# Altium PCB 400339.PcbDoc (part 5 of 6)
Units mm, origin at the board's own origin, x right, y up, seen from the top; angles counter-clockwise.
Board outline 146 x 63.5 mm, 4 copper layers (Top Layer, Mid-Layer 1, Mid-Layer 2, Bottom Layer), stack 1.505 mm thick; 400 components, 261 nets, 1523 pads, 1938 vias.
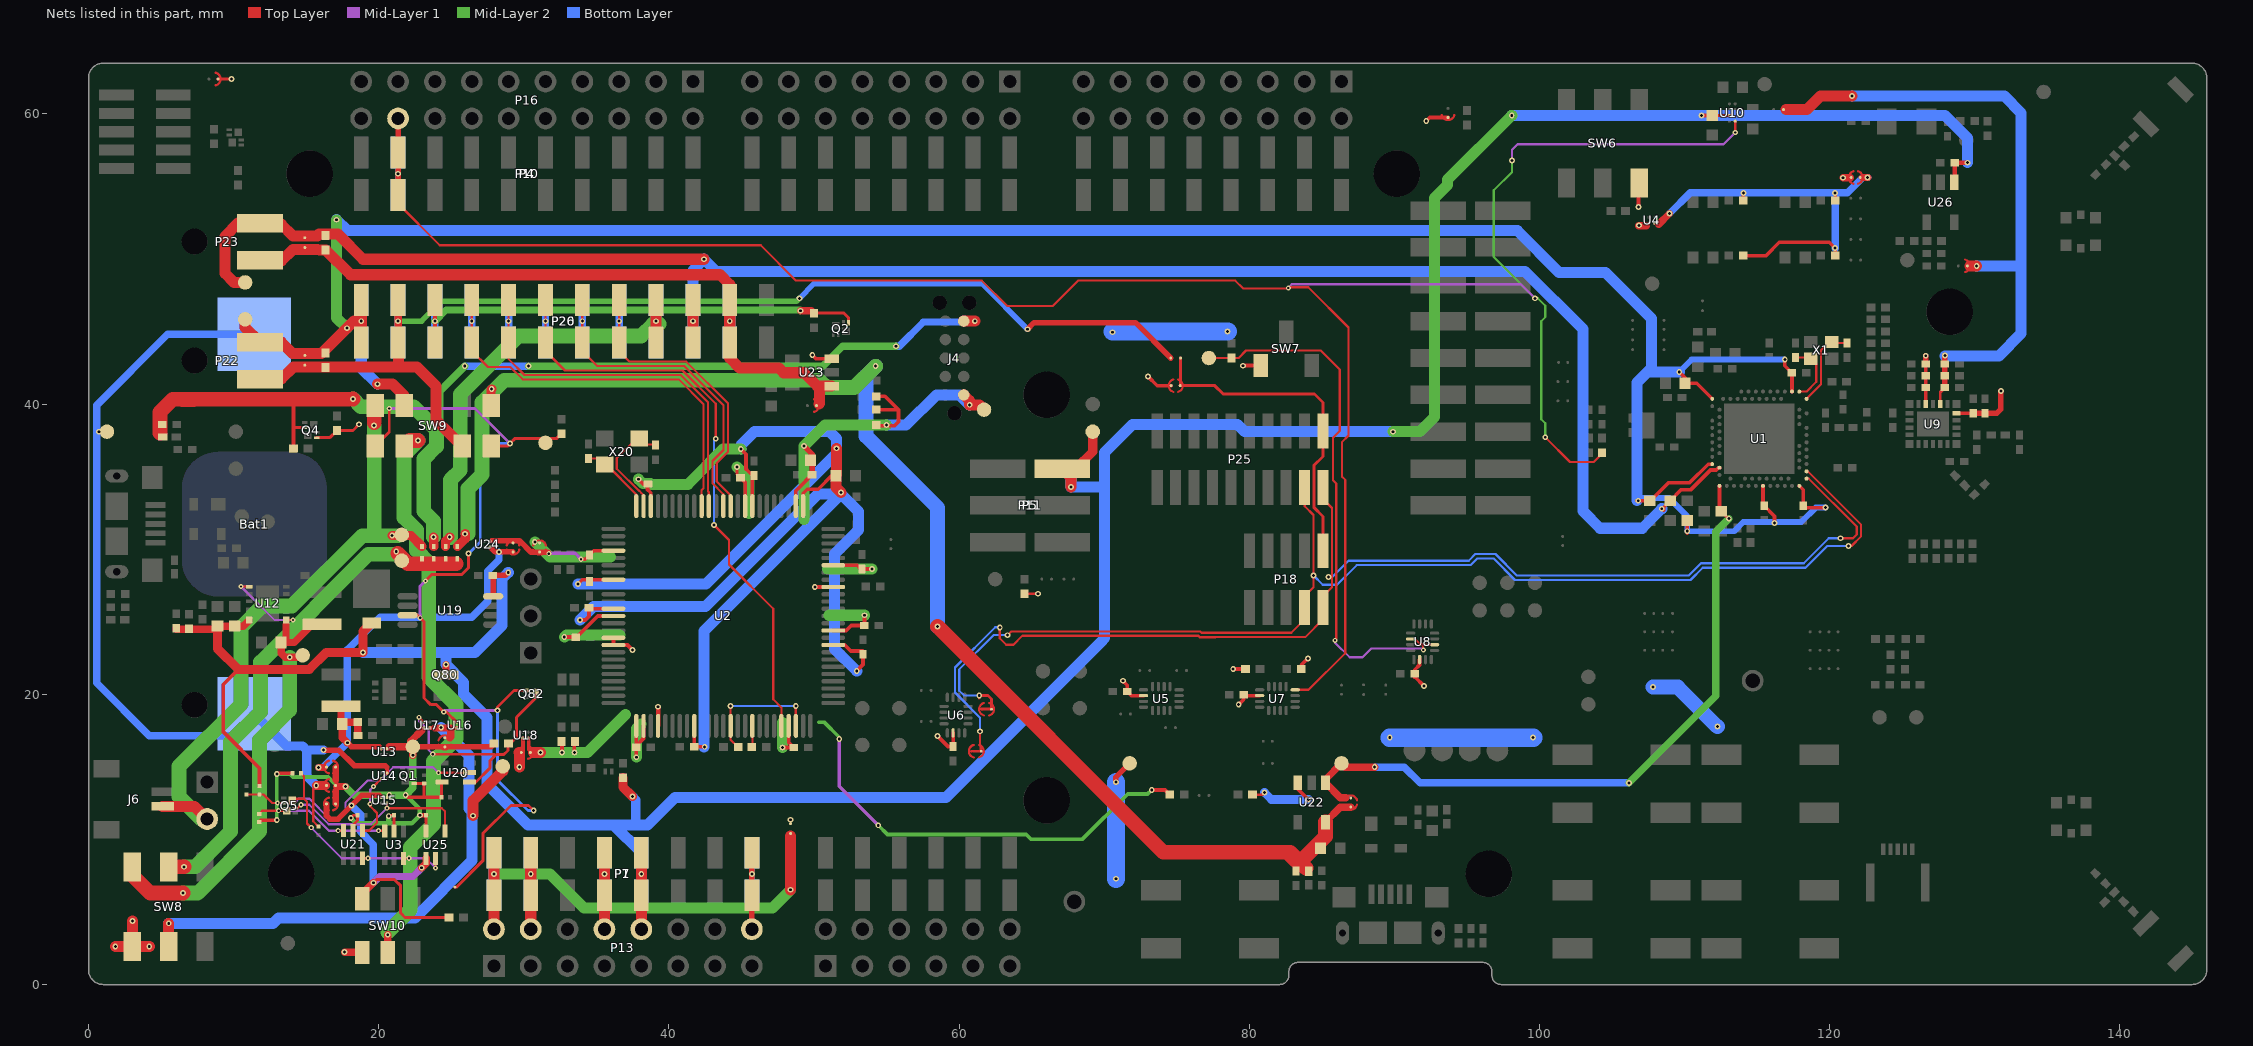
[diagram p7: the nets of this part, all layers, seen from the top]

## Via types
v1: diameter 0.4, hole 0.2, Top Layer to Bottom Layer, tented both sides, 1691 vias
v2: diameter 0.35, hole 0.15, Top Layer to Mid-Layer 1, tented both sides, 184 vias
v3: diameter 0.61, hole 0.305, Top Layer to Bottom Layer, 24 vias
v4: diameter 0.61, hole 0.305, Top Layer to Bottom Layer, tented both sides, 16 vias
v5: diameter 0.5, hole 0.3, Top Layer to Bottom Layer, tented both sides, 12 vias
v6: diameter 0.35, hole 0.15, Top Layer to Mid-Layer 1, tented top, 8 vias
v7: diameter 0.4, hole 0.2, Top Layer to Mid-Layer 1, tented top, 2 vias
v8: diameter 0.35, hole 0.15, Top Layer to Bottom Layer, tented top, 1 vias

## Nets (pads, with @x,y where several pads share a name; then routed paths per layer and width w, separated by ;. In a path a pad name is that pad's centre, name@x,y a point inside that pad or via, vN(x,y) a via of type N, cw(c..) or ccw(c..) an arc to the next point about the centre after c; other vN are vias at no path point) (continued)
SDA: P4.9 P10.9 P16.18 R1.1 U7.8 U10.D2 | length 167.8
  Top Layer w0.152: P4.9@21.336,54.415 21.336,53.823 24.206,50.952 46.329,50.952 48.767,48.514 61.568,48.514 63.321,46.761 66.452,46.761 68.205,48.514 79.037,48.514 79.579,47.972 82.649,47.972 v2(82.693,48.016) 82.736,48.059 84.071,48.059 86.843,45.288 86.843,37.838 86.385,37.38 86.385,35.009 86.614,34.78 86.614,22.835 84.089,20.31 U7.8@83.165,20.31 ; v1(100.406,37.719) 102.108,36.017 103.751,36.017 104.318,36.584 R1.1@104.318,36.66 ; v2(113.497,58.725) U10.D2@113.497,59.5
  Top Layer w0.381: P4.9@21.336,54.415 v1(21.336,55.88) P4.9@21.336,57.345 P16.18@21.336,59.69
  Mid-Layer 1 w0.152: v2(82.693,48.016) 82.937,48.26 98.73,48.26 v1(99.695,47.295) ; v1(98.12,56.792) 98.12,57.545 98.487,57.912 112.684,57.912 v2(113.497,58.725)
  Mid-Layer 2 w0.152: v1(98.12,56.792) 98.12,56.007 96.85,54.737 96.85,50.14 v1(99.695,47.295) 99.892,47.295 100.404,46.783 100.404,45.997 100.127,45.72 100.127,38.964 100.406,38.684 v1(100.406,37.719)
  Bottom Layer w0.381: P10.9@21.336,54.415 v1(21.336,55.88) P10.9@21.336,57.345
SH_GND_DETECT: P20.8 P26.8 U2.62 | length 23.2
  Top Layer w0.152: P20.8@36.576,47.185 P20.8@36.576,44.255 36.576,43.637 37.282,42.931 41.193,42.931 44.069,40.056 44.069,36.711 43.307,35.949 43.307,34.671 44.254,33.724 U2.62@44.254,32.975
  Bottom Layer w0.508: P26.8@36.576,44.255 v1(36.576,45.72) P26.8@36.576,47.185
SH_RESET: P20.7 P26.7 U2.63 | length 25.3
  Top Layer w0.152: P20.7@34.036,47.185 P20.7@34.036,44.255 34.036,43.663 35.072,42.627 41.067,42.627 43.764,39.93 43.764,36.837 43.002,36.075 43.002,34.545 43.754,33.793 U2.63@43.754,32.975
  Bottom Layer w0.508: P26.7@34.036,44.255 v1(34.036,45.72) P26.7@34.036,47.185
SH_SWDCLK: P20.5 P26.5 U2.65 | length 29.2
  Top Layer w0.152: P20.5@28.956,47.185 28.956,43.104 30.048,42.012 40.814,42.012 42.697,40.128 42.697,33.987 42.754,33.931 U2.65@42.754,32.975
  Bottom Layer w0.508: P26.5@28.956,44.255 v1(28.956,45.72) P26.5@28.956,47.185
SH_SWDIO: P20.4 P26.4 U2.66 | length 30.9
  Top Layer w0.152: P20.4@26.416,44.255 26.416,43.67 27.53,42.556 29.072,42.556 29.921,41.707 40.688,41.707 42.393,40.002 42.393,34.2 42.254,34.061 U2.66@42.254,32.975 ; P20.4@26.416,44.348 P20.4@26.416,47.185
  Bottom Layer w0.508: P26.4@26.416,44.255 v1(26.416,45.72) P26.4@26.416,47.185
SH_SWO: P20.6 P26.6 U2.21 | length 43.9
  Top Layer w0.152: P20.6@31.496,47.185 v1(31.496,45.72) P20.6@31.496,44.255 31.496,43.663 32.837,42.322 40.941,42.322 43.231,40.032 v1(43.231,37.617) ; v1(43.104,31.674) 44.145,30.632 44.145,28.955 47.193,25.907 47.193,19.66 47.754,19.099 U2.21@47.754,17.825
  Bottom Layer w0.152: v1(43.104,31.674) 43.104,37.49 v1(43.231,37.617)
  Bottom Layer w0.508: P26.6@31.496,44.255 v1(31.496,45.72) P26.6@31.496,47.185
SH_VTG: P20.3 P26.3 Q2.4 R22.1 | length 38.2
  Top Layer w0.152: P20.3@23.876,44.255 P20.3@23.876,47.185
  Top Layer w0.203: R22.1@49.996,46.271 52.072,46.271 52.387,45.955 Q2.4@52.387,45.62
  Top Layer w0.254: P20.3@23.876,44.255 v1(23.876,45.72) P20.3@23.876,47.185
  Top Layer w0.508: v1(49.073,46.436) 49.83,46.436 R22.1@49.996,46.271
  Mid-Layer 2 w0.508: v1(23.876,45.72) 24.643,46.487 49.068,46.487 49.073,46.482 v1(49.073,46.436)
  Bottom Layer w0.508: P26.3@23.876,44.255 v1(23.876,45.72) P26.3@23.876,47.185
SWDCLK: P18.4 P25.4 SB55.1 U1.AA24 | length 86.2
  Top Layer w0.152: v1@61.374,19.736 61.392,19.754 v1(61.392,19.914) ; v1(63.349,24.078) 63.607,24.335 76.624,24.335 76.71,24.249 82.897,24.249 83.82,25.171 P18.4@83.82,25.99 83.82,26.773 84.429,27.381 v1(84.429,28.194) 84.429,32.36 83.82,32.968 P25.4@83.82,34.245 ; U1.AA24@118.414,35.367 118.496,35.367 122.174,31.689 122.174,30.886 121.514,30.226
  Top Layer w0.203: v1(61.392,19.914) 62.001,19.914 62.238,19.677 62.238,19.327 SB55.1@62.238,18.974
  Bottom Layer w0.152: v1(61.392,19.914) 60.35,19.914 60.02,20.244 60.02,21.718 62.385,24.083 63.344,24.083 v1(63.349,24.078) ; v1(84.429,28.194) 85.064,27.559 86.056,27.559 87.402,28.905 95.25,28.905 95.707,29.362 96.844,29.362 98.322,27.884 110.415,27.884 111.258,28.728 118.338,28.728 119.837,30.226 v1(121.31,30.226)
SWDIO: P18.2 P25.2 SB54.1 U1.AC24 | length 88.3
  Top Layer w0.152: v1(61.443,17.45) 61.443,16.505 61.493,16.454 61.493,16.111 SB54.1@61.526,16.078 ; v1(62.81,24.616) 62.81,23.862 63.254,23.419 63.754,23.419 64.366,24.03 76.498,24.03 76.589,23.939 77.682,23.939 77.687,23.944 83.863,23.944 85.09,25.171 P18.2@85.09,25.99 85.09,26.773 85.699,27.381 85.699,32.843 85.09,33.452 P25.2@85.09,34.245 ; U1.AC24@118.414,34.867 118.565,34.867 121.869,31.563 121.869,31.012 121.616,30.759 v1(120.752,30.759)
  Bottom Layer w0.152: v1(61.443,17.45) 61.443,18.394 59.715,20.121 59.715,21.845 62.487,24.616 v1(62.81,24.616) ; 85.725,28.092 86.843,29.21 95.124,29.21 95.581,29.667 96.967,29.667 98.448,28.187 110.29,28.187 111.133,29.03 118.213,29.03 119.942,30.759 v1(120.752,30.759)
  other v1: 85.471,28.092
TCKOUT: R28.1 U2.14 U2.23 | length 8.9
  Top Layer w0.152: v1(44.254,19.197) 44.254,16.876 R28.1@44.772,16.358 ; v1(48.75,19.197) 48.75,17.837 48.758,17.829 U2.23@48.754,17.825
  Bottom Layer w0.152: v1(44.254,19.197) v1(48.75,19.197)
TMSOUT: R29.1 U2.17 | length 1.4
  Top Layer w0.152: R29.1@45.754,16.385 U2.17@45.754,17.825
TRACE_SW: R4.1 TP23.1 U8.2 U8.10 | length 37.8
  Top Layer w0.152: TP23.1@77.216,43.18 79.273,43.18 79.785,43.691 84.934,43.691 86.233,42.393 86.233,38.151 85.776,37.694 85.776,34.756 86.004,34.528 86.004,23.825 v2(85.903,23.724) ; U8.10@91.123,23.822 91.418,23.822 91.818,23.422 91.973,23.422 ; v2@91.973,23.114 91.973,23.422 ; U8.2@92.773,23.422 91.973,23.422
  Mid-Layer 1 w0.152: v2(85.903,23.724) 85.903,23.579 86.926,22.555 87.808,22.555 88.417,23.165 91.923,23.165 v2@91.999,23.089
  other v2: 91.999,23.063
V5V: C81.2 C82.2 C83.2 C85.2 C95.2 C97.2 D84.1 P1.5 P5.2 P7.5 P11.2 P13.10 Q80.2 R80.2 R83.1 R93.1 TP36.1 U10.C1 U12.10 U19.8 U26.1 | length 227.8
  Top Layer w0.203: C95.2@111.922,59.896 111.927,59.9 U10.C1@113.097,59.9
  Top Layer w0.254: 10.312,21.717 9.296,20.701 9.296,17.399 11.786,14.91 11.786,13.674 R83.1@11.782,13.671
  Top Layer w0.305: v1(111.17,59.896) C95.2@111.922,59.896 ; U26.1@128.598,55.292 128.631,55.325 C97.2@128.631,56.635 129.501,56.635 v1(129.508,56.642)
  Top Layer w0.381: C85.2@27.856,28.194 28.727,28.194 v1(28.931,28.397) ; U19.8@27.893,26.756 C85.2@27.893,28.157
  Top Layer w0.508: C81.2@6.045,24.544 6.045,24.473 C83.2@8.663,24.473 ; C83.2@8.89,24.7 C82.2@10.084,24.7 10.66,24.7 U12.10@11.04,25.079 ; Q80.2@24.639,21.336 v1(24.639,22.046)
  Top Layer w0.635: C83.2@8.89,24.7 8.89,23.139 10.312,21.717 15.215,21.717 16.383,22.885 v1(18.923,22.885) 18.923,24.334 D84.1@19.507,24.918 ; R93.1@36.83,14.257 36.83,13.614 v1(37.49,12.954) ; P5.2@67.119,35.56 68.047,35.56 69.215,36.728 TP36.1@69.215,38.1
  Top Layer w0.762: P13.10@38.1,3.81 P1.5@38.1,6.155 v1(38.1,7.62) P1.5@38.1,9.085 ; P5.2@67.119,35.56 67.722,34.957 v1(67.722,34.296)
  Mid-Layer 2 w0.762: v1(89.916,38.1) 91.767,38.1 92.773,39.106 92.773,54.206 93.675,55.108 93.675,55.474 v1(98.095,59.893)
  Bottom Layer w0.508: 21.857,22.948 21.92,22.885 ; 24.639,22.81 24.714,22.885
  Bottom Layer w0.635: v1(37.49,12.954) 37.719,12.725 37.719,10.998
  Bottom Layer w0.762: v1(18.923,22.885) 21.92,22.885 24.714,22.885 26.645,22.885 28.499,24.74 28.499,27.965 v1(28.931,28.397) ; 24.639,22.81 v1(24.639,22.046) 25.857,20.828 25.857,20.015 27.47,18.402 27.47,13.83 30.302,10.998 36.187,10.998 ; P7.5@38.1,6.155 v1(38.1,7.62) P7.5@38.1,9.085 36.187,10.998 ; P11.2@67.722,35.56 v1(67.722,34.296) 70.028,34.296 ; v1(89.916,38.1) 79.68,38.1 79.179,38.6 71.951,38.6 70.028,36.678 70.028,34.296 ; v1(98.095,59.893) 127.967,59.893 129.508,58.352 v1(129.508,56.642) ; 36.187,10.998 37.719,10.998 38.532,10.998 40.437,12.903 59.097,12.903 69.901,23.707 69.901,23.741 70.028,23.868 70.028,34.296
VBAT: Bat1.1 R18.1 SB35.2 TP26.1 U14.A1 | length 62.5
  Top Layer w0.152: v1(15.697,13.716) 15.482,13.501 15.482,11.244 R18.1@15.85,10.877
  Top Layer w0.254: U14.A1@20.571,14.576 20.571,14.959
  Top Layer w0.381: v1(16.205,16.154) 17.245,16.154 18.314,15.085 20.445,15.085 20.571,14.959
  Top Layer w0.61: v1(15.697,13.716) 16.226,13.716 SB35.2@16.332,13.716
  Bottom Layer w0.508: Bat1.1@11.43,18.654 9.921,17.145 4.191,17.145 0.559,20.777 0.559,39.929 5.446,44.816 Bat1.1@11.43,44.816
  Bottom Layer w0.635: Bat1.1@11.43,18.654 13.65,16.434 14.757,16.434 15.037,16.154 ; v1(15.697,13.716) 15.037,14.376 15.037,16.154 ; v1(16.205,16.154) 15.037,16.154
  other v1: 0.711,38.1
VBAT_EN: U14.B2 U21.4 | length 4.8
  Top Layer w0.152: U21.4@18.887,10.602 19.33,10.602 19.882,11.154 19.882,11.817 19.412,12.287 v6(19.412,12.443) v6@19.412,12.531 ; v6(19.645,13.65) U14.B2@20.171,14.176
  Mid-Layer 1 w0.152: v6(19.412,12.443) 19.412,13.418 v6(19.645,13.65)
VBOOST_SRC: C80.2 L80.2 SW8.6 TP28.1 U12.1 U12.6 | length 37.2
  Top Layer w0.152: v2(10.516,27.432) 11.056,27.432 U12.6@11.074,27.414 ; U12.1@13.614,25.114 v2(14.09,25.114)
  Top Layer w0.508: 13.614,24.816 13.614,23.871 C80.2@13.315,23.571 ; TP28.1@14.757,22.682 14.63,22.555 v1(13.868,22.555) 13.538,22.555 13.273,22.82 C80.2@13.273,23.571 C80.2@13.315,23.571 ; L80.2@16.104,24.833 15.435,24.833 14.173,23.571 C80.2@13.315,23.571
  Top Layer w1.016: SW8.6@3.028,8.109 3.028,7.529 4.258,6.299 v1(6.518,6.299)
  Mid-Layer 1 w0.152: v2(10.516,27.432) 12.834,25.114 v2(14.09,25.114)
  Mid-Layer 2 w1.016: v1(6.518,6.299) 7.518,6.299 11.786,10.566 11.786,16.84 13.868,18.923 v1(13.868,22.555)
VBOOST_SRC': D80.1 D81.1 D82.1 D83.1 SW8.5 TP32.1 | length 34.7
  Top Layer w1.016: SW8.5@5.528,8.109 v1(6.576,8.109) ; v1@21.311,29.718 22.022,29.007 25.349,29.007
  Mid-Layer 2 w1.016: v1(6.576,8.109) 7.347,8.109 9.779,10.541 9.779,16.713 11.862,18.796 11.862,22.225 19.291,29.654 21.336,29.654
  other v1: 21.209,29.845
VBUS: C69.2 D80.2 FB61.2 J4.5 Q4.2 R40.1 | length 77.7
  Top Layer w0.203: 14.13,38.384 14.144,38.397 Q4.2@14.909,38.397
  Top Layer w0.254: 13.452,40.367 14.13,40.367 14.13,40.329 14.13,38.384 R40.1@14.13,36.932
  Top Layer w0.635: v1(23.774,30.836) 23.8,30.81 D80.2@23.8,30.186
  Top Layer w0.762: J4.5@60.325,45.72 v1(61.087,45.72)
  Top Layer w1.016: 4.923,38.011 4.923,39.441 5.811,40.329 6.444,40.329 6.452,40.322 7.251,40.322 7.259,40.329 13.414,40.329 ; 13.452,40.329 14.13,40.329 18.206,40.329 v1(18.237,40.361)
  Mid-Layer 2 w0.508: 23.978,38.252 24.206,38.481 24.206,40.894 v1(25.933,42.621) ; v1(30.328,42.621) 50.597,42.621 51.968,43.993 v1(55.651,43.993)
  Mid-Layer 2 w1.016: v1(18.237,40.361) 18.771,39.827 22.403,39.827 23.978,38.252 23.978,37.084 23.114,36.22 23.114,32.614 23.774,31.953 v1(23.774,30.836)
  Bottom Layer w0.508: v1(25.933,42.621) v1(30.328,42.621) ; v1(55.651,43.993) 55.88,43.993 57.545,45.658 61.025,45.658 v1(61.087,45.72)
VBUS_NRF: C21.1 SB80.1 TP38.1 U1.AD2 U22.1 | length 47.6
  Top Layer w0.25: U1.AD2@112.414,34.367 112.414,32.742 C21.1@112.539,32.617 v1@113.053,32.103
  Top Layer w0.508: 86.656,12.878 86.272,12.878 U22.1@85.253,13.898 85.253,14.133 TP38.1@86.36,15.24 86.614,14.986 v1(88.646,14.986)
  Mid-Layer 2 w0.508: v1(106.172,13.894) 112.166,19.888 112.166,31.217 v1(113.055,32.106)
  Bottom Layer w0.508: v1(88.646,14.986) 90.678,14.986 91.77,13.894 v1(106.172,13.894)
VBUS_NRF': C68.2 C91.2 D81.2 FB60.2 SB80.2 SW9.8 U22.5 | length 100
  Top Layer w0.508: U22.5@85.253,11.198 86.272,12.217 SB80.2@86.995,12.217
  Top Layer w0.635: D81.2@25.425,30.186 25.959,30.719 v1(25.959,31.064) ; SW9.8@27.749,39.906 27.749,41.008 v1(27.788,41.046)
  Top Layer w1.016: v1(58.522,24.673) 74.076,9.119 82.634,9.119 ; 83.497,8.44 85.253,10.196 U22.5@85.253,11.198 ; 83.666,8.271 83.315,8.621 83.223,8.529 82.634,9.119 ; FB60.2@83.91,8.026 82.818,9.119 82.634,9.119
  Mid-Layer 2 w1.016: 26.162,31.064 26.162,34.188 27.127,35.154 27.127,40.132 28.651,41.656 50.368,41.656 50.876,41.148 52.781,41.148 v1(54.254,42.621)
  Bottom Layer w1.016: v1(54.254,42.621) 53.594,41.961 53.594,37.795 58.522,32.868 v1(58.522,24.673)
VCC2: C56.2 C57.2 C58.2 SB27.1 SB28.1 U9.14 | length 45.2
  Top Layer w0.203: U9.14@127.628,40.005 127.628,40.828 C56.2@127.948,41.148
  Top Layer w0.381: C56.2@127.948,41.148 C57.2@127.948,41.961 C58.2@127.948,42.774 v1(127.948,43.358)
  Top Layer w0.762: 116.986,60.302 118.449,60.302 119.386,61.239 v1(121.549,61.239) ; 129.671,49.53 v1(130.138,49.53)
  Bottom Layer w0.762: v1(121.549,61.239) 132.045,61.239 133.206,60.078 133.206,44.854 131.684,43.332 v1@127.948,43.332 ; v1(130.138,49.53) 133.182,49.53
VCORE: C24.2 C26.2 C32.1 C33.2 C35.2 C39.2 C40.2 U2.9 U2.34 U2.52 U2.59 U2.73 U2.83 U2.87 | length 120.1
  Top Layer w0.254: v1(33.747,27.598) 34.038,27.889 U2.83@36.168,27.889 ; v1(33.874,25.121) 34.232,25.121 34.501,25.389 C24.2@34.501,25.959 ; C24.2@34.67,25.9 U2.87@36.179,25.9 ; v1(37.897,34.823) 38.227,34.493 C32.1@38.531,34.493 ; C32.1@38.555,34.493 C32.1@38.531,34.493 ; U2.73@38.754,32.975 38.754,33.89 38.531,34.113 C32.1@38.531,34.493 ; C33.2@41.75,16.383 v1(42.469,16.383) ; C33.2@41.754,16.4 U2.9@41.754,17.825 ; v1(44.958,36.906) 45.314,36.551 45.314,35.525 45.466,35.373 C35.2@45.808,35.031 ; U2.59@45.754,32.975 45.754,34.977 C35.2@45.808,35.031 ; C35.2@45.862,35.085 C35.2@45.808,35.031 ; U2.52@49.254,32.975 49.254,33.861 49.531,34.138 50.292,34.138 51.232,35.077 C39.2@51.522,35.077 ; U2.34@51.329,23.4 52.13,23.4 52.543,22.987 C40.2@53.338,22.987 ; v1(52.949,21.615) 53.381,22.047 C40.2@53.381,22.766 ; C40.2@53.363,22.827 C40.2@53.363,22.987
  Top Layer w0.762: v1(51.562,36.957) 51.562,35.117 C39.2@51.522,35.077 51.522,34.254 v1(51.867,33.909)
  Mid-Layer 2 w0.762: v1(37.897,34.823) 38.202,34.519 38.718,34.519 38.769,34.468 41.3,34.468 43.739,36.906 v1(44.958,36.906)
  Bottom Layer w0.762: v1(33.747,27.598) 42.558,27.598 51.562,36.601 v1(51.562,36.957) 51.562,37.643 51.079,38.125 45.898,38.125 44.958,37.186 v1(44.958,36.906) ; v1(33.874,25.121) 34.813,26.06 42.535,26.06 50.292,33.817 v1@51.867,33.817 ; v1@42.416,16.383 42.408,16.391 42.408,24.359 v1@51.867,33.817 ; v1(52.949,21.615) 51.425,23.139 51.425,29.671 53.076,31.322 53.076,32.608 v1@51.867,33.817
VDBG: P18.1 P25.1 SB59.1 SB60.1 | length 23
  Top Layer w0.203: SB60.1@75.268,43.18 75.268,41.607 75.268,41.3 SB59.1@75.242,41.275 75.417,41.275 77.622,41.275 78.207,40.691 84.506,40.691 85.09,40.107 P25.1@85.09,38.145 85.09,36.398 84.455,35.763 84.455,32.893 85.09,32.258 P18.1@85.09,29.89
VDD: C23.2 C42.2 C45.2 C48.2 C50.2 C53.2 C54.2 C70.2 C71.2 Q4.4 R41.1 R52.1 R53.1 R54.2 R68.2 SB9.1 SB31.1 SB37.2 SB38.2 SB47.1 SB59.2 SW6.6 SW7.3 SW8.3 SW10.6 TP37.1 U4.A2 U5.14 U6.14 U7.14 U8.14 U9.11 U9.16 U18.A2 U22.3 U23.3 | length 77.1
  Top Layer w0.2: SB47.1@8.923,62.408 v1(9.855,62.408) ; R41.1@17.12,38.184 18.22,38.184 v1(18.644,38.608) ; R68.2@64.516,26.932 v1(65.448,26.932) ; R54.2@80.231,13.081 80.899,13.081 v1(81.051,13.233)
  Top Layer w0.203: Q4.4@15.724,37.687 16.623,37.687 R41.1@17.12,38.184
  Top Layer w0.254: 29.941,15.992 U18.A2@29.941,16.95 ; v1(49.886,43.383) 50.129,43.139 U23.3@51.21,43.139 ; v1(58.522,17.12) 59.241,16.4 C45.2@59.588,16.4 59.592,16.404 U6.14@59.592,17.342 ; v1(71.306,20.938) 71.306,20.922 71.595,20.633 C42.2@71.595,20.193 71.88,19.907 U5.14@72.707,19.907 ; v1(73.025,41.91) 73.66,41.275 74.443,41.275 SB59.2@74.618,41.275 ; v1@78.892,21.717 78.918,21.742 R53.1@79.739,21.742 ; v1(79.273,19.304) 79.621,19.652 C48.2@79.621,19.964 79.675,19.91 U7.14@80.715,19.91 ; v1(79.578,42.647) 79.597,42.665 SW7.3@80.8,42.665 ; U22.3@83.353,13.898 83.353,13.472 v1(84.074,12.751) ; R52.1@83.583,21.742 83.583,22.014 v1(84.049,22.479) v1@84.074,22.504 ; C50.2@91.389,21.192 91.508,21.311 C50.2@91.407,21.412 ; U8.14@91.748,22.397 91.737,22.386 91.737,22.021 91.407,21.69 C50.2@91.407,21.412 ; v1(92.05,20.574) 91.411,21.213 91.407,21.217 C50.2@91.407,21.412 ; v1(92.202,59.512) 92.448,59.759 SB31.1@93.701,59.759 ; v1(106.832,53.594) 106.832,54.948 SW6.6@106.869,54.984 ; 107.292,52.225 U4.A2@107.537,52.47 ; U9.16@126.628,40.005 C23.2@126.628,42.774 ; U9.11@128.753,39.38 129.894,39.38 C70.2@129.896,39.378
  Top Layer w0.381: v1(70.815,13.945) 70.815,14.3 TP37.1@71.755,15.24 ; C23.2@126.628,42.774 v1(126.628,43.335) ; C70.2@129.896,39.378 C71.2@130.708,39.378 131.537,39.378 131.81,39.651 v1(131.81,40.897)
  Top Layer w0.508: v1(17.653,2.235) 17.674,2.214 SW10.6@18.875,2.214 ; v1@106.858,52.299 107.366,52.299 ; v1(120.929,55.608) SB9.1@121.433,55.608
  Top Layer w0.762: v1(1.848,2.628) v1(4.185,2.628) ; SW8.3@3.027,2.559 v1(3.027,4.369) ; 29.679,15.992 29.693,15.979 v1(29.693,14.986)
  Bottom Layer w0.61: v1(81.051,13.233) 81.534,12.751 v1(84.074,12.751)
  Bottom Layer w1.016: v1(107.823,20.498) 109.55,20.498 v1(112.268,17.78)
  Bottom Layer w1.27: v1@70.587,45.009 v1(78.511,45.009) ; v1(70.815,7.29) v1(70.815,13.945) ; v1(89.687,17.018) v1(99.568,17.018)
  other v1: 48.387,11.354 78.892,21.742 70.587,44.958 106.858,52.324
VDD_HV: C19.1 P20.10 P23.1 P26.10 R91.2 SB41.1 TP25.1 U1.Y2 | length 134.4
  Top Layer w0.25: v1@108.562,32.708 108.562,32.891 C19.1@109.014,33.342 109.783,34.112 110.447,34.112 111.793,35.458 111.989,35.458 112.179,35.459 112.337,35.617 U1.Y2@112.414,35.617
  Top Layer w0.762: TP25.1@10.795,48.387 10.033,48.387 9.398,49.022 9.398,51.562 10.306,52.47 P23.1@11.811,52.47 ; P23.1@11.811,52.4 13.284,52.4 14.089,51.595 15.781,51.595 15.9,51.714 17.196,51.714 18.923,49.987 v1(42.418,49.987) ; P20.10@41.656,44.255 v1(41.656,45.72) P20.10@41.656,47.185
  Bottom Layer w0.762: P26.10@41.656,44.255 v1(41.656,45.72) P26.10@41.656,47.185 41.656,49.225 v1(42.418,49.987) 43.256,49.149 99.023,49.149 102.997,45.175 102.997,32.639 104.188,31.448 107.089,31.448 v1(108.433,32.791)
VDD_HV': P20.11 P23.2 P26.11 R91.1 SB41.2 SB81.1 U23.1 | length 50.7
  Top Layer w0.762: P23.2@11.811,49.86 13.284,49.86 14.089,50.665 15.781,50.665 ; 15.91,50.613 16.349,50.613 18.042,48.92 43.51,48.92 44.196,48.235 P20.11@44.196,47.185 v1(44.196,45.72) P20.11@44.196,44.255 44.196,43.18 44.882,42.494 47.585,42.494 47.915,42.164 49.301,42.164 50.226,41.239 ; 50.333,40.016 50.368,40.051 50.368,41.097 50.226,41.239 ; U23.1@51.21,41.239 50.226,41.239
  Bottom Layer w0.762: P26.11@44.196,44.255 v1(44.196,45.72) P26.11@44.196,47.185
VDD_NRF: C6.1 C7.1 C8.1 C12.1 C14.1 L4.1 P20.1 P22.1 P26.1 R90.2 SB40.1 SW9.6 TP24.1 U1.A22 U1.AD14 U1.AD23 U1.B1 U1.W1 | length 179.9
  Top Layer w0.25: v1@106.714,33.342 v1(106.815,33.342) C6.1@107.613,33.342 107.664,33.342 108.916,34.595 110.371,34.595 111.641,35.865 U1.W1@111.914,35.865 ; v1(109.639,42.217) 110.039,41.817 C14.1@110.039,41.444 110.837,41.444 U1.B1@111.914,40.367 ; v1@110.189,31.117 L4.1@110.189,31.992 ; C7.1@115.414,32.992 U1.AD14@115.414,34.367 ; C7.1@115.49,32.992 116.205,32.277 116.205,32.004 ; v1(116.915,43.067) 116.915,42.641 C12.1@117.389,42.167 117.414,42.142 U1.A22@117.414,40.867 ; U1.AD23@117.914,34.367 118.189,34.092 C8.1@118.189,32.992 118.313,32.868 v1(119.71,32.868)
  Top Layer w0.762: TP24.1@10.795,45.847 10.795,45.286 P22.1@11.811,44.27 13.284,44.27 14.064,43.49 16.058,43.49 v1(17.805,45.237) 18.288,45.72 v1(18.796,45.72) ; P20.1@18.796,44.255 v1(18.796,45.72) ; P20.1@18.796,47.185 v1(18.796,45.72) ; v1(19.914,41.377) 20.955,41.377 21.749,40.583 SW9.6@21.749,39.906
  Mid-Layer 2 w0.762: v1@17.094,52.685 17.094,45.949 v1(17.805,45.237)
  Bottom Layer w0.4: v1@106.714,33.342 106.731,33.36 106.894,33.522 108.946,33.522 110.189,32.28 v1@110.189,31.318 ; v1(109.639,42.217) 110.489,43.067 v1@116.839,43.067 ; v1(110.189,31.244) 113.427,31.244 114.054,31.871 118.054,31.871 119.05,32.868 v1(119.71,32.868)
  Bottom Layer w0.762: v1(17.084,52.71) 17.838,51.956 98.474,51.956 101.364,49.066 104.556,49.066 107.729,45.893 107.729,42.493 ; P26.1@18.796,47.185 v1(18.796,45.72) P26.1@18.796,44.255 18.796,42.494 v1(19.914,41.377) ; v1@106.731,33.36 106.731,41.495 107.729,42.493 ; v1(109.639,42.217) 107.729,42.217 107.729,42.493
  other v1: 116.205,31.801
VDD_NRF': P20.2 P22.2 P26.2 R90.1 SB40.2 SB60.2 SW9.3 | length 82.3
  Top Layer w0.381: v1(64.719,45.161) 65.176,45.618 72.154,45.618 SB60.2@74.592,43.18
  Top Layer w0.508: P20.2@21.336,44.255 v1(21.336,45.72) P20.2@21.336,47.185
  Top Layer w0.762: P22.2@11.811,41.73 13.284,41.73 14.115,42.561 21.361,42.561 ; P20.2@21.336,44.255 21.361,44.23 21.361,42.561 ; SW9.3@25.749,37.106 23.952,38.903 23.952,41.25 22.641,42.561 21.361,42.561
  Mid-Layer 2 w0.381: v1(21.336,45.72) 22.963,45.72 24.325,47.081 48.783,47.081 v1(48.997,47.295)
  Bottom Layer w0.381: v1(48.997,47.295) 50.013,48.311 61.57,48.311 v1(64.719,45.161)
  Bottom Layer w0.508: P26.2@21.336,44.255 v1(21.336,45.72) P26.2@21.336,47.185
VDD_NRF_SENSE: Q82.1 R88.1 SB58.1 SW9.1 SW9.4 TP33.1 U16.B2 U19.3 | length 67.1
  Top Layer w0.203: SW9.1@19.749,37.106 20.726,38.084 v2(20.726,39.7) ; U19.3@21.993,25.456 22.677,25.456 v2(22.86,25.273) 23.129,25.004 23.129,19.747 23.591,19.284 23.987,19.284 v2(24.486,18.786) 24.673,18.786 U16.B2@25.378,18.082 ; v2(23.216,27.813) 23.647,28.245 25.705,28.245 26.2,28.74 v1(26.2,29.705) ; SB58.1@25.255,6.706 25.356,6.706 27.178,8.528 27.178,10.408 29.117,12.347 30.325,12.347 v1(30.683,11.989) ; SW9.4@27.749,37.106 28.877,37.106 v1(29.058,37.287) 29.413,37.643 32.275,37.643 R88.1@32.588,37.956 ; v1(28.194,18.898) 28.194,19.126 29.333,20.266 Q82.1@30.155,20.266
  Mid-Layer 1 w0.203: v2(20.726,39.7) 26.645,39.7 v1(29.058,37.287) ; v2(22.86,25.273) 22.86,27.457 v2(23.216,27.813) ; v2(24.486,18.786) 24.597,18.898 v1(28.194,18.898)
  Bottom Layer w0.203: v1(26.2,29.705) 27,30.505 27,36.297 27.991,37.287 v1(29.058,37.287) ; v1(28.194,18.898) 28.194,14.078 30.283,11.989 v1(30.683,11.989)
VDD_PER: R47.2 R48.2 R50.2 R51.2 SB9.2 U4.A1 | length 28.9
  Top Layer w0.25: U4.A1@107.95,52.476 108.235,52.476
  Top Layer w0.254: R50.2@113.94,50.353 R50.2@114.059,50.234 115.614,50.234 116.535,51.156 119.98,51.156 v1(120.384,50.752) R51.2@120.384,50.234 ; R47.2@114.059,54.044 v1(114.059,54.562) ; R48.2@120.384,54.044 v1(120.384,54.562) ; SB9.2@122.114,55.619 122.289,55.619 ; v1(122.622,55.618) v1@122.621,55.619
  Top Layer w0.508: 108.229,52.4 v1(108.966,53.137) ; 122.289,55.619 v1@122.621,55.619
  Bottom Layer w0.508: v1(108.966,53.137) 110.391,54.562 v1(114.059,54.562) v1(120.384,54.562) ; v1(120.384,50.752) v1(120.384,54.562) ; v1(122.622,55.618) 122.293,55.618 121.237,54.562 v1(120.384,54.562)
VDD_SAM: C25.2 C31.2 C34.2 C36.2 C37.2 C38.2 C41.2 C43.2 J4.1 R20.2 R21.2 R49.2 R64.2 R65.2 R66.2 SB37.1 SB49.1 TP35.1 U2.1 U2.2 U2.4 U2.22 U2.36 U2.42 U2.45 U2.53 U2.60 U2.88 U2.91 U2.92 U18.A1 | length 117.8
  Top Layer w0.152: U2.88@36.179,25.4 U2.88@36.347,25.4
  Top Layer w0.203: v1(44.704,35.67) 44.704,35.161 C34.2@44.94,34.925
  Top Layer w0.254: 30.347,16.196 30.347,16.407 U18.A1@30.347,16.958 ; v1@32.636,16.002 R20.2@32.636,16.747 ; v1(32.791,23.952) 33.645,23.952 35.093,25.4 U2.88@36.179,25.4 ; v1(33.486,15.985) R21.2@33.486,16.747 ; U2.91@36.179,23.9 U2.92@36.179,23.4 37.151,23.4 v1(37.489,23.062) ; U2.1@37.754,17.825 37.754,16.358 37.756,16.356 v1(37.756,15.666) ; C31.2@37.76,16.459 38.254,16.954 U2.2@38.254,17.825 ; C34.2@44.94,34.925 45.254,34.611 U2.60@45.254,32.975 ; v1(47.828,16.332) C36.2@48.598,16.332 48.254,16.676 U2.22@48.254,17.825 ; U2.53@48.754,32.975 48.754,34.032 49.017,34.295 49.763,35.041 C37.2@49.763,35.128 ; U2.36@51.329,24.4 52.228,24.4 52.568,24.74 C41.2@53.465,24.74 53.482,24.757 v1(53.482,25.451) ; U2.42@51.329,27.4 U2.42@51.348,27.381 ; U2.45@51.329,28.9 52.98,28.9 C43.2@53.17,28.71 ; C43.2@53.305,28.634 v1(53.99,28.634) ; R64.2@54.293,38.557 R64.2@54.297,38.557 54.297,38.506 55.55,38.506 55.829,38.786 55.829,39.599 55.804,39.624 ; R65.2@54.293,39.624 R65.2@54.297,39.624 55.804,39.624 ; R66.2@54.297,40.538 54.889,40.538 55.804,39.624 ; v1(73.279,13.411) 74.201,13.411 R49.2@74.532,13.081
  Top Layer w0.305: U2.4@39.254,17.825 v1(39.254,19.146) ; v1(50.059,27.4) U2.42@51.329,27.4
  Top Layer w0.381: v1(49.317,37.109) 49.868,36.559 C37.2@49.868,35.128
  Top Layer w0.762: 30.678,15.992 v1(31.16,15.992) ; J4.1@60.325,40.64 60.731,40.234 v1(60.731,39.954) 61.417,39.954 TP35.1@61.747,39.624
  Mid-Layer 1 w0.254: v1(51.74,16.916) 51.74,13.665 v1(54.432,10.973)
  Mid-Layer 2 w0.254: 50.343,18.085 50.698,18.085 51.74,17.043 v1(51.74,16.916) ; v1(54.432,10.973) 55.07,10.335 64.625,10.335 64.94,10.02 68.513,10.02 71.622,13.129 72.997,13.129 v1(73.279,13.411)
  Mid-Layer 2 w0.762: v1(30.759,30.505) 31.801,29.464 35.992,29.464 ; v1@31.16,15.985 v1(33.486,15.985) 34.377,15.985 37.004,18.612 ; v1(32.791,23.952) 32.937,24.098 36.623,24.098 ; v1(37.756,15.666) 37.756,17.639 38.075,17.958 ; v1(44.704,35.67) 45.513,34.861 45.513,32.48 ; v1(47.828,16.332) 47.828,18.053 ; 49.317,32.045 v1(49.317,37.109) 50.765,38.557 v1(55.008,38.557) ; 50.948,28.634 v1(53.99,28.634) ; 51.024,25.451 v1(53.482,25.451)
  Bottom Layer w0.762: v1(55.008,38.557) 56.354,38.557 58.437,40.64 60.046,40.64 v1(60.731,39.954)
  other v1: 32.636,15.985
VDD_UTMI: C28.2 SB48.1 SB49.2 U2.79 U24.A1 | length 9.2
  Top Layer w0.254: v2@31.681,29.787 v2@31.775,29.693 ; v2(33.95,29.312) 34.237,29.312 C28.2@34.534,29.608 ; C28.2@34.542,29.616 34.826,29.9 U2.79@36.179,29.9
  Top Layer w0.381: 27.788,30.596 29.704,30.596 30.513,29.787 30.757,29.787 31.422,29.787 v2@31.681,29.787
  Mid-Layer 1 w0.254: v2@31.725,29.718 33.543,29.718 v2(33.95,29.312)
  other v2: 31.725,29.693
VEXT: R92.1 SB36.2 SW10.3 U15.A1 U25.1 | length 24.7
  Top Layer w0.203: SW10.3@18.875,5.914 SW10.3@18.875,6.251 ; v1(19.634,7.01) 19.865,7.241 21.08,7.241 21.514,6.807 21.514,4.928 21.819,4.623 R92.1@24.849,4.623
  Top Layer w0.381: SB36.2@16.403,12.446 16.403,12.093 16.403,11.63 16.629,11.405 17.2,11.405 18.825,13.03 20.041,13.03 U15.A1@20.104,12.967
  Top Layer w0.508: SW10.3@18.875,6.251 v1(19.634,7.01) ; v7(22.964,8.047) 23.273,8.356 U25.1@23.273,8.693
  Mid-Layer 1 w0.508: v1(19.634,7.01) 20.071,7.447 22.364,7.447 v7(22.964,8.047)
  Bottom Layer w0.508: v1(18.136,12.331) 18.754,11.713 18.754,10.528 19.634,9.648 v1(19.634,7.01)
VEXT_EN: Q5.5 U15.B2 U25.4 | length 13.2
  Top Layer w0.152: Q5.5@14.257,12.151 14.406,12.151 v2(14.646,12.391) ; U15.B2@20.571,12.5 20.571,12.157 v6(20.565,12.151) 24.355,12.151 24.573,11.933 U25.4@24.573,10.593
  Mid-Layer 1 w0.152: v2(14.646,12.391) 15.211,12.391 16.564,11.039 19.453,11.039 v6(20.565,12.151)
VEXT_EN_INV: Q5.3 R89.2 U3.6 U21.6 | length 10.2
  Top Layer w0.152: R89.2@11.76,11.766 11.975,11.981 v2(13.106,11.981) Q5.3@13.65,11.981 ; v2(17.209,10.602) U21.6@17.587,10.602 ; v2(19.99,10.602) 20.407,10.602 U3.6@20.415,10.594
  Mid-Layer 1 w0.152: v2(13.106,11.981) 15.19,11.981 16.569,10.602 v2(17.209,10.602) v2(19.99,10.602)
VIN: P1.8 P7.8 P13.16 | length 8.2
  Top Layer w0.381: P13.16@45.72,3.81 P1.8@45.72,6.155 v1(45.72,7.62) P1.8@45.72,9.085
  Bottom Layer w0.381: P7.8@45.72,6.155 v1(45.72,7.62) P7.8@45.72,9.085
VIN3-5V: D83.2 P20.9 P26.9 | length 32.5
  Top Layer w0.635: D83.2@24.613,30.186 24.613,30.556 v1(24.892,30.836)
  Top Layer w0.762: P20.9@39.116,44.255 v1(39.116,45.72) P20.9@39.116,47.185
  Mid-Layer 2 w1.016: v1@24.943,30.785 24.943,34.773 25.629,35.458 25.629,40.691 29.642,44.704 38.1,44.704 38.913,45.517 39.319,45.517
  Bottom Layer w0.762: P26.9@39.116,44.255 v1(39.116,45.72) P26.9@39.116,47.185
VIO: P1.1 P1.2 P1.4 P7.1 P7.2 P7.4 P13.2 P13.4 P13.8 SB38.1 | length 54.1
  Top Layer w0.381: v1(35.56,7.62) P1.4@35.56,9.085
  Top Layer w0.762: P13.2@27.94,3.81 P1.1@27.94,6.155 P1.1@27.94,9.085 ; P13.4@30.48,3.81 v1(30.48,7.62) P1.2@30.48,9.085 ; P13.8@35.56,3.81 P1.4@35.56,9.085 ; v1(48.387,6.528) 48.387,10.236
  Mid-Layer 2 w0.762: v1(27.94,7.62) v1(30.48,7.62) 31.801,7.62 34.138,5.283 35.535,5.283 ; v1(35.56,7.62) 35.56,5.309 35.535,5.283 ; v1(48.387,6.528) 47.142,5.283 35.535,5.283
  Bottom Layer w0.762: P7.1@27.94,6.155 P7.1@27.94,9.085 ; P7.2@30.48,6.155 P7.2@30.48,9.085 ; P7.4@35.56,6.155 P7.4@35.56,9.085
VLI-ION: D82.2 J6.2 P27.2 SW9.5 TP31.1 | length 44.1
  Top Layer w0.635: v1(20.93,30.937) 22.235,30.937 D82.2@22.987,30.186
  Top Layer w0.762: J6.2@5.105,12.276 7.307,12.276 P27.2@8.179,11.405
  Top Layer w1.016: 19.685,38.735 19.685,39.842 SW9.5@19.749,39.906
  Mid-Layer 2 w1.016: P27.2@8.179,11.405 7.772,11.405 6.236,12.941 6.236,15.05 10.516,19.329 10.516,24.613 11.989,26.086 14.021,26.086 18.872,30.937 19.685,30.937 ; v1(19.685,38.532) 19.685,30.937 ; 21.336,30.937 v1(20.93,30.937) 19.685,30.937
VREG: C87.2 C88.2 L81.2 R82.2 SB34.2 SB48.2 U13.A1 U24.A2 | length 33
  Top Layer w0.254: 20.033,16.391 U13.A1@20.171,16.253
  Top Layer w0.381: v1(17.845,16.662) 18.117,16.391 20.033,16.391 ; 27.788,30.062 27.774,30.062 28.024,29.812 v1(28.296,29.812) 28.908,29.812 SB48.2@29.235,29.812
  Top Layer w0.508: v1(15.85,14.961) 16.228,14.961 16.23,14.959 ; L81.2@17.399,19.093 17.399,18.049 C88.2@17.49,17.958 ; v1(17.845,16.662) 17.49,17.018 C88.2@17.49,17.958 ; C87.2@18.575,17.17 18.55,17.196 R82.2@18.55,18.085 17.617,18.085 C88.2@17.49,17.958
  Bottom Layer w0.508: v1(15.85,14.961) 16.144,14.961 v1(17.845,16.662) 17.845,23.078 20.091,25.324 26.406,25.324 27.508,26.426 27.508,28.499 28.296,29.286 v1(28.296,29.812)
VREG_EN: Q5.2 R83.2 R85.1 U20.2 | length 18.3
  Top Layer w0.152: R85.1@10.893,13.101 R83.2@11.782,13.101 12.064,13.101 12.654,12.511 v2(13.03,12.511) Q5.2@13.442,12.511 ; v2(24.116,14.599) 25.925,14.599 U20.2@25.918,14.605
  Mid-Layer 1 w0.152: v2(13.03,12.511) 14.194,12.511 14.48,12.797 15.237,12.797 16.599,11.434 17.102,11.434 17.704,12.036 17.704,12.519 19.249,14.064 20.095,14.064 21.009,14.977 23.738,14.977 v2(24.116,14.599)
VREG_EN_INV: Q5.6 R86.2 U3.3 U21.3 U25.2 | length 16
  Top Layer w0.152: Q5.6@14.05,12.681 14.166,12.797 14.858,12.797 15.062,12.593 15.062,11.097 v2(15.352,10.807) ; R86.2@14.636,14.554 14.851,14.339 14.851,12.804 ; U21.3@18.887,8.702 v2(19.254,8.702) ; U3.3@21.715,8.694 22.09,8.694 v2(22.098,8.702) ; v2(23.923,8.027) U25.2@23.923,8.693
  Mid-Layer 1 w0.152: v2(15.352,10.807) 17.457,8.702 v2(19.254,8.702) v2(22.098,8.702) 23.248,8.702 v2(23.923,8.027)
VSENSE_SW_OUT: SB39.1 SW8.2 TP30.1 U16.A2 U17.A1 | length 41
  Top Layer w0.25: U17.A1@23.517,17.682 23.876,17.682 ; 24.971,17.682 U16.A2@25.378,17.682
  Top Layer w0.508: 23.876,17.682 24.971,17.682 24.971,17.08 24.905,17.013 24.892,17
  Top Layer w0.762: SW8.2@5.528,2.609 v1(5.528,4.216) ; v1(26.492,11.633) 26.492,12.665 28.55,14.722 TP30.1@28.55,14.859
  Bottom Layer w0.762: v1(5.528,4.216) 12.727,4.216 13.106,4.596 22.503,4.596 26.441,8.534 26.441,11.909 26.225,12.125 26.225,15.786 v1(24.308,17.704)
VSRC_NRF: SW9.2 SW10.5 | length 40
  Top Layer w0.508: SW10.5@20.625,2.214 v1(20.625,3.429)
  Top Layer w1.016: SW9.2@21.749,37.106 22.133,37.49 v1(22.708,37.49)
  Mid-Layer 2 w1.016: v1@20.625,3.607 22.174,5.156 22.174,9.449 23.777,11.051 23.777,15.389 25.329,16.942 25.329,19.298 23.444,21.184 23.444,29.083 22.606,29.921 22.606,31.32 21.749,32.177 21.749,36.532 v1(22.708,37.49)
VSUPPLY: C89.2 C90.2 C93.2 C103.2 Q1.4 R6.1 R86.1 R87.1 R89.1 SB34.1 SB35.1 SB36.1 SB39.2 TP29.1 U3.5 U13.A2 U15.A2 U17.A2 U20.5 U21.5 U25.5 | length 46.8
  Top Layer w0.203: v1(18.079,11.475) 18.267,11.664 C89.2@18.535,11.664 18.535,11.299 18.237,11.001 U21.5@18.237,10.602 ; v1(20.693,11.601) 20.756,11.664 C103.2@21.051,11.664 21.051,10.608 U3.5@21.065,10.594 ; Q1.4@22.455,13.851 23.125,13.851 R6.1@23.129,13.855 23.129,12.917 23.143,12.902 ; C90.2@23.269,11.664 23.269,10.597 U25.5@23.273,10.593 ; C93.2@24.336,12.902 24.336,13.943 U20.5@24.348,13.955
  Top Layer w0.254: R89.1@11.76,11.196 11.893,11.328 v1(12.979,11.328) ; v1(12.979,14.503) 13.03,14.554 13.851,14.554 ; U13.A2@20.571,16.253 20.707,16.389 ; v1(21.86,13.056) 22.014,12.902 23.143,12.902 C93.2@24.336,12.902
  Top Layer w0.305: v1(22.843,11.664) C90.2@23.269,11.664
  Top Layer w0.381: TP29.1@22.758,16.391 23.937,16.391 23.942,16.386 24.201,16.386 24.922,16.386 27.722,16.386 R87.1@27.948,16.612
  Top Layer w0.457: SB36.1@17.028,12.446 17.028,12.799 17.028,13.365 ; 17.028,14.067 17.028,14.633 SB34.1@17.028,14.986
  Top Layer w0.508: SB35.1@17.091,13.65 17.195,13.65 v1(17.704,13.65) ; 20.707,16.389 22.085,16.389 22.222,16.253 22.222,16.786 22.962,17.526 ; v1(22.352,15.799) TP29.1@22.352,16.383
  Mid-Layer 2 w0.203: 20.695,11.102 20.695,11.151
  Mid-Layer 2 w0.254: v1(12.979,11.328) v1(12.979,14.503) 13.868,14.503 14.072,14.3 16.51,14.3 17.16,13.65 v1(17.704,13.65)
  Mid-Layer 2 w0.305: v1(18.079,11.475) 18.079,11.471 18.448,11.102 20.695,11.102 22.28,11.102 v1(22.843,11.664) 22.843,12.073 v1(21.86,13.056)
  Mid-Layer 2 w0.381: v1(20.693,11.601) 20.693,11.153 20.695,11.151
  Mid-Layer 2 w0.508: v1(17.704,13.65) 18.298,13.056 v1(20.727,13.056) v1(21.86,13.056) 22.352,13.548 v1(22.352,15.799)
VSUPPLY_EN: Q82.3 R87.2 U17.B2 U20.1 | length 16.8
  Top Layer w0.152: v2(22.784,18.415) U17.B2@23.117,18.082 ; v2(23.724,15.875) 27.983,15.875 28.059,15.799
  Top Layer w0.203: U20.1@25.918,13.955 26.706,13.955 27.661,14.91 27.661,15.4 28.059,15.799 28.11,15.85 28.626,15.85 28.905,16.129 28.905,16.62 29.066,16.62 29.489,17.043 29.489,18.415 30.855,19.781 Q82.3@30.855,20.041
  Mid-Layer 1 w0.152: v2(22.784,18.415) 22.784,18.161 23.444,17.501 23.444,16.154 v2(23.724,15.875)
XC1: C1.1 U1.B24 X1.1 | length 5.8
  Top Layer w0.152: U1.B24@118.414,40.367 119.414,41.367 119.414,43.717 119.909,44.213 C1.1@121.203,44.213
XC2: C2.1 U1.A23 X1.3 | length 4.3
  Top Layer w0.152: C2.1@117.647,43.213 118.625,43.213 X1.3@118.7,43.138 119.089,42.749 119.089,41.538 118.418,40.867 U1.A23@117.914,40.867
XIN: C29.1 U2.75 X20.3 | length 5.1
  Top Layer w0.152: C29.1@34.458,36.254 35.162,36.254 X20.3@35.575,35.841 ; X20.3@35.575,35.838 35.694,35.838 37.754,33.778 U2.75@37.754,32.975
XOUT: C30.1 U2.74 X20.1 | length 7.5
  Top Layer w0.152: U2.74@38.254,32.975 38.254,33.729 38.1,33.884 37.955,34.029 37.934,34.029 36.414,35.549 36.414,36.287 37.746,37.619 X20.1@37.963,37.619 38.354,37.228 C30.1@39.081,37.228
pads on no net: A1.2 A2.2 Bat1.0 Fid1.0 Fid2.0 J2.4 J2.6@1.944,28.45 J2.6@1.944,35.05 J3.4 J3.6@86.429,3.557 J3.6@93.029,3.557 J4.0 J4.7 J4.9 J5.0 J5.1 J5.3 J5.5 J6.0 P18.7 P18.8 P19.7 P19.8 P21.0 P22.0 P23.0 P25.7 P25.8 P25.11 P25.13 SW8.1 U2.6 U2.8 U2.10 U2.11 U2.13 U2.15 U2.16 U2.19 U2.25 U2.26 U2.28 U2.29 U2.30 U2.31 U2.32 U2.33 U2.37 U2.44 U2.48 U2.49 U2.50 U2.58 U2.64 U2.69 U2.86 U2.93 U2.94 U2.95 U2.96 U2.99 U2.100 U5.1 U5.5 U5.9 U5.13 U6.1 U6.5 U6.9 U6.13 U7.7 U7.11 U8.11 U8.12 U8.13 U12.5 U22.4 U23.4

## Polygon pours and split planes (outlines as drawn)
VDD on Mid-Layer 2 "Mid_Layer_2-VDD" (solid, remove dead copper, pour order 10): 0,0 0,63.5 146.025,63.5 146.025,0
VDD_SAM on Mid-Layer 2 "Mid_Layer_2-VDD_SAM" (solid, pour order 8): 35.837,33.12 35.837,17.379 51.555,17.379 51.555,33.12
GND on Bottom Layer "Bottom_Layer-GND" (solid, remove dead copper, pour order 6): 0,0 0,63.5 146.025,63.5 146.025,0
GND on Mid-Layer 1 "Mid_Layer_1-GND" (solid, remove dead copper, pour order 7): 0,0 0,63.5 146.025,63.5 146.025,0
GND on Top Layer "Top_Layer-GND" (solid, remove dead copper, pour order 12): 0,0 0,63.5 146.025,63.5 146.025,0

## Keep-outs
Top Layer:
  lines w0.152: 16.336,8.023 ccw(c13.97,7.62) 16.339,8.006 ; 68.406,13.103 ccw(c66.04,12.7) 68.409,13.086 ; 90.89,53.591 cw(c90.17,55.88) 91.893,54.209
Mid-Layer 1:
  circle w0.152: c66.04,12.7 r2.4
  circle w0.152: c90.17,55.88 r2.4
  circle w0.152: c13.97,7.62 r2.4
Mid-Layer 2:
  circle w0.152: c90.17,55.88 r2.4
  circle w0.152: c13.97,7.62 r2.4
  lines w0.152: 65.381,10.392 cw(c66.04,12.7) 66.72,10.398
Bottom Layer:
  circle w0.152: c66.04,12.7 r2.4
  circle w0.152: c90.17,55.88 r2.4
  circle w0.152: c13.97,7.62 r2.4
Keep-Out Layer:
  circle w0.1: c146,19.904 r0.3
  circle w0.1: c146,18.804 r0.3
  circle w0.1: c146,17.705 r0.3
  circle w0.1: c146,50.891 r0.3
  circle w0.1: c146,49.792 r0.3
  circle w0.1: c146,48.692 r0.3
  circle w0.152: c128.27,46.355 r2.4
  circle w0.152: c15.24,55.88 r2.4
  circle w0.152: c66.04,40.64 r2.4
  circle w0.152: c96.52,7.62 r2.4
  circle w0.1: c13.967,0 r0.3
  circle w0.1: c15.067,0 r0.3
  circle w0.1: c16.167,0 r0.3
  circle w0.1: c123.987,0 r0.3
  circle w0.1: c122.887,0 r0.3
  circle w0.1: c121.787,0 r0.3
  circle w0.1: c121.787,63.5 r0.3
  circle w0.1: c122.887,63.5 r0.3
  circle w0.1: c123.987,63.5 r0.3
  circle w0.1: c13.967,63.5 r0.3
  circle w0.1: c15.067,63.5 r0.3
  circle w0.1: c16.167,63.5 r0.3
  circle w0.1: c0,48.692 r0.3
  circle w0.1: c0,49.792 r0.3
  circle w0.1: c0,50.891 r0.3
  circle w0.1: c0,17.705 r0.3
  circle w0.1: c0,18.804 r0.3
  circle w0.1: c0,19.904 r0.3
  lines w0.254: 0,1.016 ccw(c1.016,1.016) 1.016,0 82.099,0 ccw(c82.099,0.635) 82.734,0.635 82.734,0.889 cw(c83.369,0.889) 83.369,1.524 96.09,1.524 cw(c96.09,0.889) 96.725,0.889 96.725,0.635 ccw(c97.36,0.635) 97.36,0 144.984,0 ccw(c144.984,1.016) 146,1.016 146,62.484 ccw(c144.984,62.484) 144.984,63.5 1.016,63.5 ccw(c1.016,62.484) 0,62.484 0,1.016

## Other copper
Top Layer:
  rectangle net GND: 8.484,25.527 12.167,26.594
  rectangle net GND: 11.557,24.308 13.132,28.397
  pour cut-out: 24.34,36.179 34.579,36.18 cw(c34.58,33.644) 36.375,35.436 38.509,33.302 cw(c36.718,31.508) 39.253,31.506 39.253,31.237 cw(c37.043,31.237) 37.043,29.027 34.834,29.027 cw(c34.833,30.64) 33.693,29.5 31.579,31.613 ccw(c30.81,30.846) 30.808,31.933 24.328,31.933 cw(c135.433,33.762)
  pour cut-out: 13.807,35.551 cw(c15.316,34.043) 15.316,36.176 25.908,36.176 25.908,31.939 16.574,31.92 ccw(c16.747,30.866) 15.922,31.544 14.783,30.405 13.807,30.405
  pour cut-out: 9.86,34.155 11.774,34.155 11.938,34.155 11.938,30.013 11.169,30.013 cw(c11.169,30.94) 10.513,30.284 ccw(c10.035,29.809) 10.034,30.482 5.422,30.482 5.422,34.158 7.355,34.158 7.411,34.148 7.465,34.13 7.51,34.104 7.553,34.069 7.584,34.023 7.602,33.98 7.607,33.934 7.607,32.685 9.354,32.685 9.354,33.65 cw(c9.86,33.65)
  pour cut-out: 11.677,34.155 12.282,34.155 ccw(c12.282,34.476) 12.509,34.249 13.819,35.56 14.795,35.56 14.795,30.414 cw(c13.804,31.435) 13.782,30.013 11.677,30.013
  pour cut-out: 90.658,5.004 90.658,7.315 96.62,7.315 96.62,5.004
  pour cut-out: 91.161,32.131 91.161,33.401 89.891,33.401 89.891,32.131
  pour cut-out: 107.164,32.217 107.164,33.617 110.834,33.617 110.834,32.217
  pour cut-out: 110.664,31.367 110.664,32.867 113.164,32.867 113.164,31.367
  pour cut-out: 115.414,36.867 115.414,38.367 117.914,38.367 117.914,36.867
  pour cut-out: 117.737,33.63 116.676,34.691 118.444,36.458 119.505,35.398
  pour cut-out: 60.528,30.937 68.073,30.937 68.071,32.715 60.528,32.715
  pour cut-out: -0.229,28.204 2.824,28.204 2.818,35.281 -0.228,35.281
  pour cut-out: 28.981,25.603 28.981,26.873 27.711,26.873 27.711,25.603
  pour cut-out: 118.567,26.975 117.297,26.975 117.297,25.705 118.567,25.705
  pour cut-out: 11.252,51.765 9.982,51.765 9.982,50.495 11.252,50.495
  pour cut-out: 86.385,35.687 85.115,35.687 85.115,34.417 86.385,34.417
  pour cut-out: 60.757,53.086 48.387,53.086 48.387,51.816 60.757,51.816
  pour cut-out: 107.163,43.256 107.163,44.526 105.054,44.526 105.054,43.256
  pour cut-out: 22.149,1.168 22.149,2.438 20.879,2.438 20.879,1.168
  pour cut-out: 20.447,5.715 20.447,6.985 19.177,6.985 19.177,5.715
  pour cut-out: 20.218,1.143 20.218,3.264 18.948,3.264 18.948,1.143
  pour cut-out: 11.252,43.635 9.982,43.635 9.982,42.365 11.252,42.365
  pour cut-out: 118.496,37.293 121.239,37.293 121.239,39.142 120.439,39.142 120.439,40.188 118.496,40.188
Mid-Layer 1:
  pour cut-out: 100.424,39.133 100.424,43.637 102.799,43.637 102.799,39.133
  pour cut-out: 110.633,46.154 110.633,47.457 111.908,47.457 111.908,46.154
  pour cut-out: 28.315,29.007 28.315,31.318 32.137,31.318 32.137,29.007
  pour cut-out: 92.078,58.763 92.078,61.074 95.377,61.074 95.377,58.763
  pour cut-out: 48.603,38.976 48.603,41.288 50.978,41.288 50.978,38.976
  pour cut-out: 85.782,11.379 85.782,13.691 88.157,13.691 88.157,11.379
  pour cut-out: 110.28,27.254 110.28,21.336 106.28,21.336 106.28,27.254
  pour cut-out: 121.71,25.984 121.71,20.066 117.71,20.066 117.71,25.984
  pour cut-out: 104.44,46.723 110.357,46.723 110.357,42.723 104.44,42.723
  pour cut-out: 15.45,11.278 15.45,16.104 17.824,16.104 17.824,11.278
  pour cut-out: 23.4,15.494 23.4,17.805 25.774,17.805 25.774,15.494
  pour cut-out: 75.724,11.938 75.724,14.249 78.098,14.249 78.098,11.938
  pour cut-out: 56.725,19.202 56.725,21.514 59.099,21.514 59.099,19.202
  pour cut-out: 56.598,17.094 56.598,19.406 58.972,19.406 58.972,17.094
  pour cut-out: 60.618,17.843 60.618,20.155 62.992,20.155 62.992,17.843
  pour cut-out: 59.969,14.973 59.969,17.285 62.344,17.285 62.344,14.973
  pour cut-out: 64.878,26.695 64.878,29.007 68.656,29.007 68.656,26.695
  pour cut-out: 120.612,48.831 120.612,57.137 122.987,57.137 122.987,48.831
  pour cut-out: 7.449,61.138 7.449,63.449 9.823,63.449 9.823,61.138
  pour cut-out: 70.263,17.45 70.263,19.761 72.637,19.761 72.637,17.45
  pour cut-out: 71.438,20.587 71.438,22.898 73.812,22.898 73.812,20.587
  pour cut-out: 74.175,20.512 74.175,22.823 76.549,22.823 76.549,20.512
  pour cut-out: 73.369,16.612 73.369,18.923 75.744,18.923 75.744,16.612
  pour cut-out: 28.448,14.884 28.448,17.196 31.747,17.196 31.747,14.884
  pour cut-out: 54.212,29.184 54.212,31.495 56.586,31.495 56.586,29.184
  pour cut-out: 80.042,13.995 80.042,18.161 82.416,18.161 82.416,13.995
  pour cut-out: 84.979,19.177 84.979,21.488 90.941,21.488 90.941,19.177
  pour cut-out: 13.678,49.898 13.678,52.21 16.053,52.21 16.053,49.898
  pour cut-out: 13.704,41.87 13.704,44.181 16.078,44.181 16.078,41.87
  pour cut-out: 47.232,9.614 47.232,11.925 49.606,11.925 49.606,9.614
  pour cut-out: 23.654,5.486 23.654,7.798 26.028,7.798 26.028,5.486
  pour cut-out: 73.641,41.986 73.641,44.298 76.016,44.298 76.016,41.986
  pour cut-out: 73.667,40.03 73.667,42.342 76.041,42.342 76.041,40.03
Bottom Layer:
  pour cut-out: 35.56,27.407 34.29,27.407 34.29,26.137 35.56,26.137

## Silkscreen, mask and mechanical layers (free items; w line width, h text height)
Top Overlay:
  drawing of 81 lines, arcs and shapes, not listed
  text "nRF ONLY" at 97.765,62.052 h1.78
  text "DEFAULT" at 104.877,62.052 h1.78
  text "GND" at 91.389,61.709 h1.78
  text "GND" at 11.125,61.62 h1.78
  text "LED1" at 109.622,54.654 h2.03
  text "LED2" at 115.82,54.654 h2.03
  text "Debug out" at 0.406,54.127 h2.03
  text "P0.11" at 87.757,52.781 h1.78
  text "P0.12" at 99.584,52.781 h1.78
  text "LED3" at 109.495,50.869 h2.03
  text "LED4" at 115.845,50.869 h2.03
  text "VDD_HV" at 1.016,50.775 h1.4
  text "P0.13" at 87.757,50.241 h1.78
  text "P0.14" at 99.584,50.241 h1.78
  text "P0.27" at 19.304,49.886 h1.78 r90
  text "P0.26" at 21.844,49.886 h1.78 r90
  text "P0.02" at 24.384,49.886 h1.78 r90
  text "GND" at 26.924,49.886 h1.78 r90
  text "P1.15" at 29.464,49.886 h1.78 r90
  text "P1.14" at 32.004,49.886 h1.78 r90
  text "P1.13" at 34.544,49.886 h1.78 r90
  text "P1.12" at 37.084,49.886 h1.78 r90
  text "P1.11" at 39.624,49.886 h1.78 r90
  text "P1.10" at 42.164,49.886 h1.78 r90
  text "P1.08" at 46.228,49.886 h1.78 r90
  text "P1.07" at 48.768,49.886 h1.78 r90
  text "P1.06" at 51.308,49.886 h1.78 r90
  text "P1.05" at 53.848,49.886 h1.78 r90
  text "P1.04" at 56.388,49.886 h1.78 r90
  text "P1.03" at 58.928,49.886 h1.78 r90
  text "P1.02" at 61.468,49.886 h1.78 r90
  text "P0.10" at 69.088,49.886 h1.78 r90
  text "P0.09" at 71.628,49.886 h1.78 r90
  text "P0.08" at 74.168,49.886 h1.78 r90
  text "P0.07" at 76.708,49.886 h1.78 r90
  text "P0.06" at 79.248,49.886 h1.78 r90
  text "P0.05" at 81.788,49.886 h1.78 r90
  text "P0.01" at 84.328,49.886 h1.78 r90
  text "P0.00" at 86.868,49.886 h1.78 r90
  text "P0.15" at 87.757,47.701 h1.78
  text "P0.16" at 99.584,47.701 h1.78
  text "nRF current" at 0.965,47.193 h2.03
  text "measurement" at 0.483,45.898 h2.03
  text "Alt." at 79.756,45.339 h1.78
  text "Def." at 83.439,45.339 h1.78
  text "P0.17" at 87.757,45.161 h1.78
  text "P0.18" at 99.584,45.161 h1.78
  text "GPIO" at 102.997,44.958 h1.52
  text "P0.20" at 99.584,43.744 h1.78
  text "XTAL" at 102.997,43.688 h1.52
  text "P0.19" at 87.757,42.621 h1.78
  text "VDD" at 1.016,42.57 h1.4
  text "VTG" at 24.308,41.056 h1.4 r90
  text "VDD / nRF" at 19.761,40.98 h1.4 r90
  text "VDD / nRF'" at 22.301,40.98 h1.4 r90
  text "(ARDUINO D0) P1.01" at 64.059,40.777 h1.78 r90
  text "SWD / IO" at 27.508,40.752 h1.4 r90
  text "SWD / CLK" at 30.048,40.752 h1.4 r90
  text "SWO" at 31.928,40.74 h1.4 r90
  text "TRACE" at 80.391,40.513 h1.78
  text "P0.21" at 87.757,40.081 h1.78
  text "VIN / 3-5V" at 40.081,39.993 h1.4 r90
  text "RESET" at 34.519,39.811 h1.4 r90
  text "VDD / nRF_HV" at 42.621,39.028 h1.4 r90
  text "VDD / nRF_HV'" at 45.161,39.028 h1.4 r90
  text "GND / DETECT" at 37.617,38.963 h1.4 r90
  text "P0.22" at 99.584,38.722 h1.78
  text "P0.23" at 87.757,37.541 h1.78
  text "P0.24" at 99.584,36.932 h1.78
  text "P1.14" at 57.767,35.082 h1.52
  text "5V" at 69.248,35.031 h1.52
  text "P0.25" at 87.757,35.001 h1.78
  text "P1.00" at 99.584,35.001 h1.78
  text "Li-Po   VDD   USB" at 18.313,34.95 h1.78
  text "nRF power source" at 17.424,33.299 h2.03
  text "P1.13" at 69.248,32.567 h1.52
  text "P1.15" at 57.717,32.542 h1.52
  text "P1.09" at 87.757,32.461 h1.78
  text "GND" at 99.584,32.461 h1.78
  text "DETECT" at 69.16,30.074 h1.52
  text "RESET" at 56.955,30.002 h1.52
  text "Debug in" at 79.477,23.12 h2.03
  text "External supply" at 0.279,22.454 h2.03
  text "SB20-22" at 106.934,22.225 h1.52 r90
  text "SB10-12" at 110.465,22.225 h1.52 r90
  text "GND" at 113.414,22.195 h1.78
  text "SB13-15" at 118.364,21.463 h1.52 r90
  text "SB23-25" at 121.92,21.463 h1.52 r90
  text "-" at 13.741,19.939 h1.52
  text "+" at 13.741,17.399 h1.52
  text "Button 1" at 102.594,17.19 h2.29
  text "Button 2" at 112.641,17.19 h2.29
  text ".PCBRevision" at 144.928,16.887 h1.52 r90
  text "nRF52840-DK w/FEM" at 141.964,16.817 h2.54 r90
  text ".PCBNumber" at 143.625,16.822 h2.03 r90
  text "Li-po" at 3.251,15.088 h2.03
  text "-" at 5.715,13.513 h1.02
  text "+" at 5.715,10.973 h1.02
  text "N.C." at 46.253,10.465 h1.78 r90
  text "VDD" at 28.365,10.462 h1.78 r90
  text "VDD" at 30.905,10.462 h1.78 r90
  text "RESET" at 33.445,10.462 h1.78 r90
  text "VDD" at 35.985,10.462 h1.78 r90
  text "5V" at 38.525,10.462 h1.78 r90
  text "GND" at 41.065,10.462 h1.78 r90
  text "GND" at 43.605,10.462 h1.78 r90
  text "P0.03 (A0)" at 51.225,10.462 h1.78 r90
  text "P0.04" at 53.765,10.462 h1.78 r90
  text "P0.28" at 56.305,10.462 h1.78 r90
  text "P0.29" at 58.845,10.462 h1.78 r90
  text "P0.30" at 61.385,10.462 h1.78 r90
  text "P0.31" at 63.925,10.462 h1.78 r90
  text "NFC" at 123.123,9.926 h2.29
  text "Button 4" at 112.691,8.011 h2.29
  text "Button 3" at 102.518,8 h2.29
  text "IF BOOT/RESET" at 71.907,7.785 h2.03
  text "nRF USB" at 86.298,7.131 h2.29
  text "VEXT   nRF" at 16.662,6.756 h2.03
  text "GND" at 69.393,5.156 h1.78
  text "Power" at 11.506,3.2 h2.03 r90
  text "GND" at 68.402,0.761 h1.78
  text "ON" at 2.911,0.229 h1.78
  text "OFF" at 5.655,0.229 h1.78
  text "OFF" at 18.009,0.203 h1.78
  text "ON" at 21.438,0.203 h1.78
